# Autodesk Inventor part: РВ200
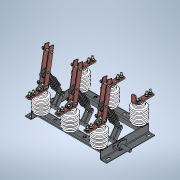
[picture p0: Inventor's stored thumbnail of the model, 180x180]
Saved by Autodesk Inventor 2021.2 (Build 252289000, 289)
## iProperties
Created: 1900-01
Part Number: РВ200
Material: Типовые
Description: STEP AP242
Document SubType Name: Modeling
Designer: pc
Density: 1 g/cm^3
Appearance: По умолчанию
Company: UNSPECIFIED
Title: ÐÂ200
Author: UNSPECIFIED
Revision Number: ANYUNSPECIFIED
Sending System: C3D Toolkit
Preprocessor: C3D Converter
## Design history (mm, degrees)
feature "БазТело1"
feature "БазТело2"
feature "БазТело3"
feature "БазТело4"
feature "БазТело5"
feature "Составной1"
node "Твердое тело1"
node "Твердое тело2"
node "Твердое тело3"
node "Твердое тело4"
node "Твердое тело5"
body "SRF1"
